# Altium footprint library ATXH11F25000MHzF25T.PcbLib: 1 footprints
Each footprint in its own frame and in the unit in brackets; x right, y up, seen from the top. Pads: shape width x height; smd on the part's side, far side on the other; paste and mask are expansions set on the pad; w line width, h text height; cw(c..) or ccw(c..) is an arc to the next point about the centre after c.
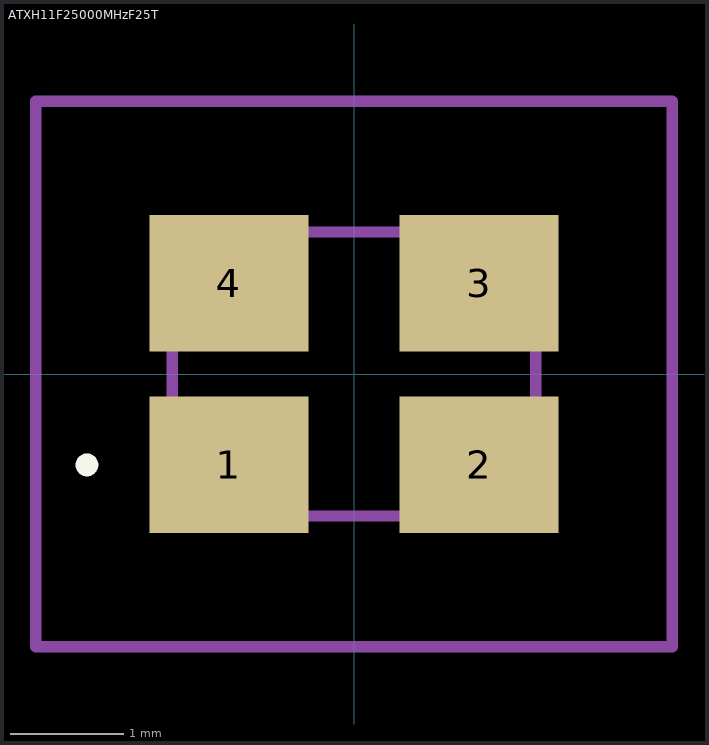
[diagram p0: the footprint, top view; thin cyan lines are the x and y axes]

## ATXH11F25000MHzF25T [mm]
pads (4):
  rect 1.4x1.2 smd: 1(-1.1,-0.8) 2(1.1,-0.8) 3(1.1,0.8) 4(-1.1,0.8)
Top Overlay:
  lines w0.1: -2.4,-0.8 -2.4,-0.8 ; -2.4,-0.8 ccw(c-2.35,-0.8) -2.3,-0.8 ; -2.4,-0.8 cw(c-2.35,-0.8) -2.3,-0.8 ; -2.3,-0.8 -2.3,-0.8
Mechanical 15:
  lines w0.1: -1.6,-1.25 1.6,-1.25 1.6,1.25 -1.6,1.25 -1.6,-1.25
Mechanical 20:
  lines w0.1: -2.8,-2.4 2.8,-2.4 2.8,2.4 -2.8,2.4 -2.8,-2.4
